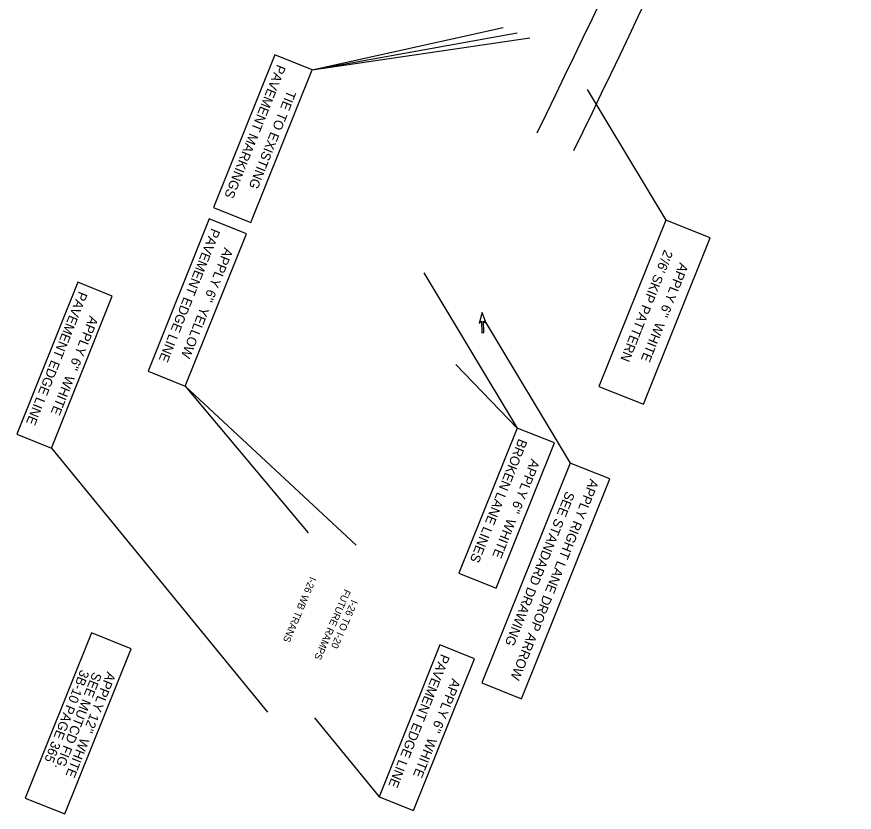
# Model space of a CAD drawing. Extents: x 1966013 to 1974896, y 789499 to 804826.
# Drawn here: x 1967905 to 1968605, y 795524 to 796189 of the extents above; entities that cross this region are included whole.
import ezdxf

# ---------------------------------------------------------------- set-up
doc = ezdxf.new("R2010")
doc.units = 0
for name, color, linetype in [('RD_EX_Conc', 7, 'Continuous'), ('RD_EX_H2O_BlueLn', 7, 'Continuous'), ('RD_HC_Cl', 7, 'Continuous'), ('RD_PD_ALT5_CL', 7, 'Continuous'), ('RD_PD_MedBWall', 7, 'Continuous')]:
    doc.layers.add(name, color=color, linetype=linetype)

msp = doc.modelspace()

# ---------------------------------------------------------------- linework, layer by layer
at = {"layer": 'RD_EX_Conc'}
for p, q in [((1968294.3, 795942), (1968291.71, 795932.89)), ((1968297.59, 795933.12), (1968294.3, 795942)), ((1968291.71, 795932.89), (1968293.69, 795934.65)), ((1968293.69, 795934.65), (1968294.06, 795925.06)), ((1968295.86, 795925.13), (1968295.49, 795934.72)), ((1968295.49, 795934.72), (1968297.59, 795933.12)), ((1968294.06, 795925.06), (1968295.86, 795925.13))]:
    msp.add_line(p, q, dxfattribs=at)
at = {"layer": 'RD_EX_H2O_BlueLn'}
for p, q in [((1968152.17, 796144.61), (1968311.84, 796179.98)), ((1968152.17, 796144.61), (1968323.54, 796175.45)), ((1968152.17, 796144.61), (1968334.23, 796171.36)), ((1968382.15, 796128.25), (1968447.8, 796019.17)), ((1968245.73, 795974.92), (1968323.67, 795845.4)), ((1968296.32, 795935.28), (1968368, 795816.16)), ((1968272.26, 795898.44), (1968323.67, 795845.4)), ((1968046.14, 795880.3), (1968148.8, 795757.82)), ((1968046.14, 795880.3), (1968189.12, 795747.44)), ((1967934.23, 795828.71), (1968115.03, 795608.09)), ((1968154.2, 795603.21), (1968208.14, 795537.4))]:
    msp.add_line(p, q, dxfattribs=at)
for points in [[(1968121.09, 796157.09), (1968069.91, 796029.64), (1968100.99, 796017.15), (1968152.17, 796144.61)], [(1968066.25, 796020.23), (1968015.07, 795892.78), (1968046.14, 795880.3), (1968097.33, 796007.75)], [(1968447.8, 796019.17), (1968391.98, 795880.18), (1968429.1, 795865.27), (1968484.92, 796004.26)], [(1967956.26, 795967.17), (1967905.31, 795840.32), (1967934.23, 795828.71), (1967985.17, 795955.56)], [(1968323.67, 795845.4), (1968274.92, 795724.02), (1968305.97, 795711.55), (1968354.72, 795832.93)], [(1968368, 795816.16), (1968294.21, 795632.43), (1968327.19, 795619.18), (1968400.98, 795802.92)], [(1967967.84, 795674.18), (1967912.48, 795536.33), (1967945.46, 795523.09), (1968000.82, 795660.93)], [(1968259.08, 795664.25), (1968208.14, 795537.4), (1968237.05, 795525.79), (1968288, 795652.64)]]:
    msp.add_lwpolyline(points, close=True, dxfattribs=at)
at = {"layer": 'RD_HC_Cl'}
msp.add_arc((1959629.02, 800353.92), 9698, 333.931286, 337.27075, dxfattribs=at)
at = {"layer": 'RD_PD_ALT5_CL'}
msp.add_arc((1959629.02, 800353.92), 9732, 333.931286, 337.272759, dxfattribs=at)

# ---------------------------------------------------------------- texts
at = {"layer": 'RD_EX_H2O_BlueLn'}
for s, height, rotation, p in [('PAVEMENT MARKINGS', 7.9995, 248.11897, (1968122.99, 796149.64)), ('TIE TO EXISTING', 7.9996, 248.11897, (1968131.6, 796128.12)), ('PAVEMENT EDGE LINE', 7.9995, 248.11897, (1968068.15, 796012.78)), ("APPLY 6''  YELLOW", 7.9996, 248.11897, (1968078.93, 795996.69)), ("2'/6' SKIP PATTERN", 7.9991, 248.11916, (1968446.64, 795994.83)), ("APPLY 6''  WHITE", 7.9992, 248.11916, (1968459.57, 795984.09)), ('PAVEMENT EDGE LINE', 7.9995, 248.11897, (1967957.28, 795960.12)), ("APPLY 6''  WHITE", 7.9996, 248.11897, (1967966.32, 795939.68)), ('BROKEN LANE LINES', 8.0004, 248.11897, (1968324.94, 795837.05)), ("APPLY 6''  WHITE", 7.9995, 248.11897, (1968335.38, 795820.11)), ('APPLY RIGHT LANE DROP ARROW', 7.9995, 248.11897, (1968384.65, 795803.43)), ('SEE STANDARD DRAWING', 7.9995, 248.11897, (1968364.55, 795793.15)), ('PAVEMENT EDGE LINE', 7.9995, 248.11897, (1968260.11, 795657.2)), ('3B-10 PAGE 365', 7.9995, 248.11897, (1967958.77, 795644.03)), ('SEE MUTCD FIG.', 7.9995, 248.11897, (1967969.2, 795642.22)), ("APPLY 12''  WHITE", 7.9996, 248.11897, (1967980.92, 795642.34)), ("APPLY 6''  WHITE", 7.9996, 248.11897, (1968269.14, 795636.76))]:
    msp.add_text(s, height=height, rotation=rotation, dxfattribs=at).set_placement(p)
at = {"layer": 'RD_PD_MedBWall'}
for s, rotation, p in [('I-26 WB TRANS', 247.07104, (1968150.48, 795721.69)), ('FUTURE RAMPS ', 246.30155, (1968179.23, 795711.29)), ('I-26 TO I-20 ', 246.30155, (1968185.17, 795702.44))]:
    msp.add_text(s, height=5.9996, rotation=rotation, dxfattribs=at).set_placement(p)

doc.saveas('drawing.dxf')
